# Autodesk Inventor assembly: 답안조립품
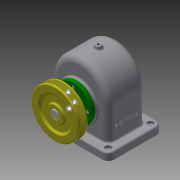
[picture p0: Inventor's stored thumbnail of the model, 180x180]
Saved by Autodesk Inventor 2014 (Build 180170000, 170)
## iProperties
Created: 2016-10
Part Number: 답안조립품
Document SubType Name: Assembly
Designer: USER
Author: USER
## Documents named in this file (15)
- C:\Users\USER\Desktop\461008V1012\답안조립품.iam
- C:\Users\USER\Desktop\461008V1012\본체.ipt
- C:\Users\USER\Desktop\461008V1012\앞커버.ipt
- C:\Users\USER\Desktop\461008V1012\베어링 6203.ipt
- C:\Users\USER\Desktop\461008V1012\뒤커버.ipt
- C:\Users\USER\Desktop\461008V1012\축.ipt
- C:\Users\USER\Desktop\461008V1012\키 - 6 x 6 x 22.ipt
- C:\Users\USER\Desktop\461008V1012\스퍼기어.ipt
- C:\Users\USER\Desktop\461008V1012\키 - 5 x 5 x 18.ipt
- C:\Users\USER\Desktop\461008V1012\V-벨트풀리.ipt
- C:\Users\USER\Desktop\461008V1012\오일씰 28 40 8.ipt
- C:\Users\USER\Desktop\461008V1012\볼트 M3 x 8.ipt
- C:\Users\USER\Desktop\461008V1012\볼트 M3 x 10.ipt
- C:\Users\USER\Desktop\461008V1012\부시.ipt
- C:\Users\USER\Desktop\461008V1012\멈춤나사 - M4x10.ipt
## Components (9 placed, 3 different names)
1. V-벨트풀리:1
2. ISO 4762 M3 x 8:1
3. ISO 4762 M3 x 8:2
4. ISO 4762 M3 x 8:3
5. ISO 4762 M3 x 8:4
6. ISO 4762 M3 x 10:1
7. ISO 4762 M3 x 10:2
8. ISO 4762 M3 x 10:3
9. ISO 4762 M3 x 10:4
